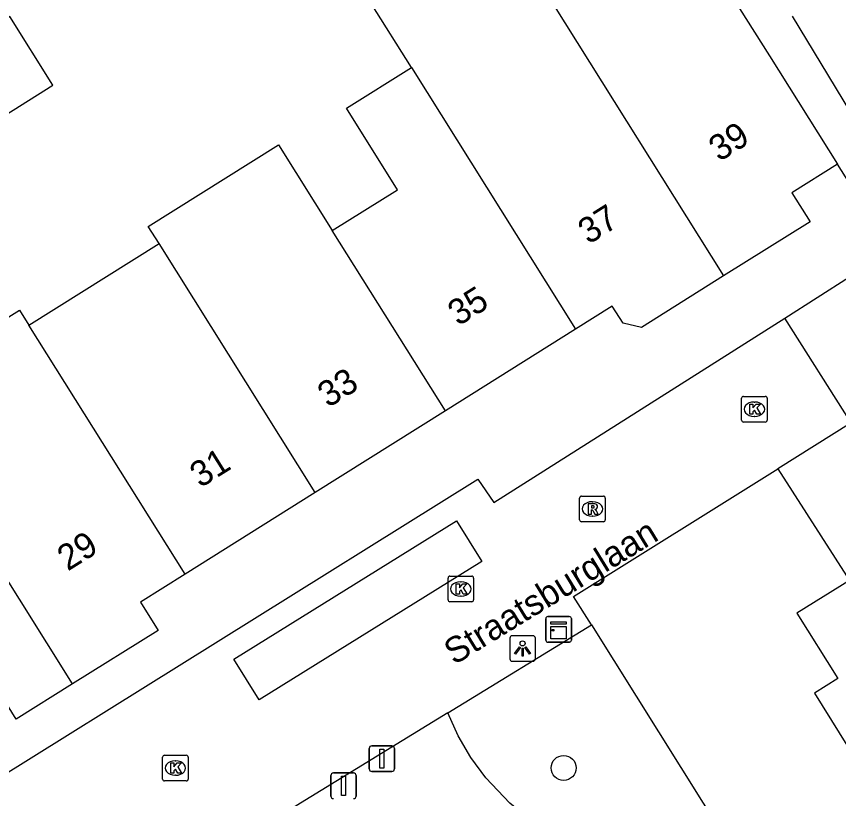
# Model space of a CAD drawing. Extents: x 157767 to 159171, y 387842 to 389425.
# Drawn here: x 158662.43 to 158694.55, y 388250.18 to 388280.75 of the extents above; entities that cross this region are included whole.
import ezdxf

# ---------------------------------------------------------------- set-up
doc = ezdxf.new("R2010")
doc.units = 0
for name, color, linetype in [('IMGEO_Afsluitpaal', 7, 'Continuous'), ('IMGEO_Boom', 7, 'Continuous'), ('IMGEO_Groenvoorziening', 7, 'Continuous'), ('IMGEO_Kast', 7, 'Continuous'), ('IMGEO_Kolk', 7, 'Continuous'), ('IMGEO_Lichtpunt', 7, 'Continuous'), ('IMGEO_Muur', 7, 'Continuous'), ('IMGEO_Openbare_ruimte_label', 7, 'Continuous'), ('IMGEO_Pand', 7, 'Continuous'), ('IMGEO_Pand_nummerreeks', 7, 'Continuous'), ('IMGEO_Rijbaan_lokaal_open', 7, 'Continuous'), ('IMGEO_Rioolput', 7, 'Continuous'), ('IMGEO_Voetpad_open', 7, 'Continuous')]:
    doc.layers.add(name, color=color, linetype=linetype)

msp = doc.modelspace()

# ---------------------------------------------------------------- linework, layer by layer
at = {"layer": 'IMGEO_Afsluitpaal'}
for p, q in [((158676.307, 388252.237), (158677.097, 388252.237)), ((158677.097, 388252.237), (158676.307, 388252.237)), ((158676.207, 388251.337), (158676.207, 388252.137)), ((158676.207, 388252.137), (158676.207, 388251.337)), ((158677.197, 388252.137), (158677.197, 388251.337)), ((158677.197, 388251.337), (158677.197, 388252.137)), ((158677.097, 388251.237), (158676.307, 388251.237)), ((158676.307, 388251.237), (158677.097, 388251.237)), ((158674.71, 388250.278), (158674.71, 388251.078)), ((158674.71, 388251.078), (158674.71, 388250.278)), ((158674.81, 388251.178), (158675.6, 388251.178)), ((158675.6, 388251.178), (158674.81, 388251.178)), ((158675.7, 388251.078), (158675.7, 388250.278)), ((158675.7, 388250.278), (158675.7, 388251.078))]:
    msp.add_line(p, q, dxfattribs=at)
for points in [[(158676.627, 388252.112), (158676.777, 388252.112), (158676.777, 388251.362), (158676.627, 388251.362), (158676.627, 388252.112)], [(158675.13, 388251.053), (158675.28, 388251.053), (158675.28, 388250.303), (158675.13, 388250.303), (158675.13, 388251.053)]]:
    msp.add_lwpolyline(points, dxfattribs=at)
for centre, start, end in [((158676.307, 388252.137), 90, 180), ((158676.307, 388252.137), 90, 180), ((158677.097, 388252.137), 0, 90), ((158677.097, 388252.137), 360, 90), ((158676.307, 388251.337), 180, 270), ((158676.307, 388251.337), 180, 270), ((158677.097, 388251.337), 270, 0), ((158677.097, 388251.337), 270, 0), ((158674.81, 388251.078), 90, 180), ((158674.81, 388251.078), 90, 180), ((158675.6, 388251.078), 0, 90), ((158675.6, 388251.078), 360, 90), ((158674.81, 388250.278), 180, 270), ((158674.81, 388250.278), 180, 270), ((158675.6, 388250.278), 270, 0), ((158675.6, 388250.278), 270, 0)]:
    msp.add_arc(centre, 0.1, start, end, dxfattribs=at)
at = {"layer": 'IMGEO_Boom'}
msp.add_circle((158683.805, 388251.375), 0.489, dxfattribs=at)
at = {"layer": 'IMGEO_Groenvoorziening'}
msp.add_lwpolyline([(158696.668, 388238.183), (158694.905, 388237.153), (158694.43, 388236.939), (158693.909, 388236.937), (158693.432, 388237.147), (158693.064, 388237.565), (158689.892, 388242.059), (158688.18, 388244.196), (158686.325, 388246.211), (158681.698, 388249.994), (158680.762, 388250.987), (158680.18, 388251.781), (158679.685, 388252.632), (158679.282, 388253.53)], dxfattribs=at)
at = {"layer": 'IMGEO_Kast'}
for p, q in [((158683.11, 388256.365), (158683.11, 388257.206)), ((158683.11, 388257.206), (158683.11, 388256.365)), ((158683.185, 388257.29), (158684.026, 388257.29)), ((158684.026, 388257.29), (158683.185, 388257.29)), ((158684.11, 388257.215), (158684.11, 388256.374)), ((158684.11, 388256.374), (158684.11, 388257.215)), ((158684.035, 388256.29), (158683.194, 388256.29)), ((158683.194, 388256.29), (158684.035, 388256.29))]:
    msp.add_line(p, q, dxfattribs=at)
for points in [[(158683.305, 388257.08), (158683.905, 388257.08), (158683.905, 388256.995), (158683.305, 388256.995), (158683.305, 388257.08)], [(158683.305, 388256.905), (158683.905, 388256.905), (158683.905, 388256.416), (158683.305, 388256.416), (158683.305, 388256.905)]]:
    msp.add_lwpolyline(points, dxfattribs=at)
msp.add_circle((158683.389, 388256.754), 0.0377, dxfattribs=at)
for centre, start, end in [((158683.188, 388257.212), 92.4484, 184.2845), ((158683.188, 388257.212), 92.4484, 184.2845), ((158684.032, 388257.212), 2.4484, 94.2845), ((158684.032, 388257.212), 2.4484, 94.2845), ((158683.188, 388256.368), 182.4484, 274.2845), ((158683.188, 388256.368), 182.4484, 274.2845), ((158684.032, 388256.368), 272.4484, 4.2845), ((158684.032, 388256.368), 272.4484, 4.2845)]:
    msp.add_arc(centre, 0.0779, start, end, dxfattribs=at)
at = {"layer": 'IMGEO_Kolk'}
for p, q in [((158690.758, 388264.969), (158690.758, 388265.821)), ((158690.833, 388265.895), (158691.685, 388265.895)), ((158691.246, 388265.675), (158691.271, 388265.675)), ((158691.759, 388265.821), (158691.759, 388264.969)), ((158691.269, 388265.115), (158691.244, 388265.115)), ((158691.685, 388264.895), (158690.833, 388264.895)), ((158679.288, 388257.945), (158679.288, 388258.797)), ((158679.363, 388258.871), (158680.215, 388258.871)), ((158679.776, 388258.651), (158679.801, 388258.651)), ((158680.289, 388258.797), (158680.289, 388257.945)), ((158679.799, 388258.091), (158679.774, 388258.091)), ((158680.215, 388257.871), (158679.363, 388257.871)), ((158668.21, 388251.869), (158669.062, 388251.869)), ((158668.135, 388250.943), (158668.135, 388251.795)), ((158668.623, 388251.649), (158668.648, 388251.649)), ((158669.136, 388251.795), (158669.136, 388250.943)), ((158669.062, 388250.869), (158668.21, 388250.869)), ((158668.646, 388251.089), (158668.621, 388251.089))]:
    msp.add_line(p, q, dxfattribs=at)
for points in [[(158690.758, 388264.969), (158690.758, 388265.821)], [(158690.833, 388265.895), (158691.685, 388265.895)], [(158691.759, 388265.821), (158691.759, 388264.969)], [(158691.079, 388265.595), (158691.202, 388265.595), (158691.202, 388265.444), (158691.332, 388265.595), (158691.496, 388265.595), (158691.35, 388265.444), (158691.503, 388265.195), (158691.351, 388265.195), (158691.266, 388265.359), (158691.202, 388265.292), (158691.202, 388265.195), (158691.079, 388265.195), (158691.079, 388265.595)], [(158691.685, 388264.895), (158690.833, 388264.895)], [(158679.288, 388257.945), (158679.288, 388258.797)], [(158679.363, 388258.871), (158680.215, 388258.871)], [(158680.289, 388258.797), (158680.289, 388257.945)], [(158679.609, 388258.571), (158679.732, 388258.571), (158679.732, 388258.42), (158679.862, 388258.571), (158680.026, 388258.571), (158679.88, 388258.42), (158680.033, 388258.171), (158679.881, 388258.171), (158679.796, 388258.335), (158679.732, 388258.268), (158679.732, 388258.171), (158679.609, 388258.171), (158679.609, 388258.571)], [(158680.215, 388257.871), (158679.363, 388257.871)], [(158668.21, 388251.869), (158669.062, 388251.869)], [(158668.135, 388250.943), (158668.135, 388251.795)], [(158668.456, 388251.569), (158668.579, 388251.569), (158668.579, 388251.418), (158668.709, 388251.569), (158668.873, 388251.569), (158668.727, 388251.418), (158668.88, 388251.169), (158668.728, 388251.169), (158668.643, 388251.333), (158668.579, 388251.266), (158668.579, 388251.169), (158668.456, 388251.169), (158668.456, 388251.569)], [(158669.136, 388251.795), (158669.136, 388250.943)], [(158669.062, 388250.869), (158668.21, 388250.869)]]:
    msp.add_lwpolyline(points, dxfattribs=at)
for centre, start, end in [((158690.835, 388265.819), 91.552, 178.448), ((158690.835, 388265.819), 91.552, 178.448), ((158691.683, 388265.819), 1.552, 88.448), ((158691.683, 388265.819), 1.552, 88.448), ((158690.835, 388264.971), 181.552, 268.448), ((158690.835, 388264.971), 181.552, 268.448), ((158691.683, 388264.971), 271.552, 358.448), ((158691.683, 388264.971), 271.552, 358.448), ((158679.365, 388258.795), 91.552, 178.448), ((158679.365, 388258.795), 91.552, 178.448), ((158680.213, 388258.795), 1.552, 88.448), ((158680.213, 388258.795), 1.552, 88.448), ((158679.365, 388257.947), 181.552, 268.448), ((158679.365, 388257.947), 181.552, 268.448), ((158680.213, 388257.947), 271.552, 358.448), ((158680.213, 388257.947), 271.552, 358.448), ((158668.212, 388251.793), 91.552, 178.448), ((158668.212, 388251.793), 91.552, 178.448), ((158669.06, 388251.793), 1.552, 88.448), ((158669.06, 388251.793), 1.552, 88.448), ((158668.212, 388250.945), 181.552, 268.448), ((158668.212, 388250.945), 181.552, 268.448), ((158669.06, 388250.945), 271.552, 358.448), ((158669.06, 388250.945), 271.552, 358.448)]:
    msp.add_arc(centre, 0.0765, start, end, dxfattribs=at)
for centre, major_axis, ratio, start_param, end_param in [((158691.245, 388265.395), (-0.387, 0.002), 0.722429, 4.712389, 7.853982), ((158691.27, 388265.395), (-0.39, 0.002), 0.717154, 1.570796, 4.712389), ((158679.775, 388258.371), (-0.387, 0.002), 0.722429, 4.712389, 7.853982), ((158679.8, 388258.371), (-0.39, 0.002), 0.717154, 1.570796, 4.712389), ((158668.622, 388251.369), (-0.387, 0.002), 0.722429, 4.712389, 7.853982), ((158668.647, 388251.369), (-0.39, 0.002), 0.717154, 1.570796, 4.712389)]:
    msp.add_ellipse(centre, major_axis=major_axis, ratio=ratio, start_param=start_param, end_param=end_param, dxfattribs=at)
at = {"layer": 'IMGEO_Lichtpunt'}
for p, q in [((158681.704, 388256.446), (158681.704, 388255.639)), ((158681.704, 388256.446), (158681.704, 388255.639)), ((158682.606, 388256.541), (158681.798, 388256.541)), ((158682.606, 388256.541), (158681.798, 388256.541)), ((158682.7, 388255.639), (158682.7, 388256.446)), ((158682.7, 388255.639), (158682.7, 388256.446)), ((158681.798, 388255.545), (158682.606, 388255.545)), ((158681.798, 388255.545), (158682.606, 388255.545))]:
    msp.add_line(p, q, dxfattribs=at)
for points in [[(158682.078, 388256.11), (158682.117, 388256.082), (158681.929, 388255.82), (158681.891, 388255.847), (158682.078, 388256.11)], [(158682.18, 388256.062), (158682.227, 388256.062), (158682.227, 388255.74), (158682.18, 388255.74), (158682.18, 388256.062)], [(158682.29, 388256.082), (158682.328, 388256.109), (158682.515, 388255.847), (158682.476, 388255.819), (158682.29, 388256.082)]]:
    msp.add_lwpolyline(points, dxfattribs=at)
msp.add_circle((158682.203, 388256.244), 0.0994, dxfattribs=at)
for centre, start, end in [((158681.798, 388256.446), 90, 180), ((158681.798, 388256.446), 90, 180), ((158682.606, 388256.446), 0, 90), ((158682.606, 388256.446), 0, 90), ((158681.798, 388255.639), 180, 270), ((158681.798, 388255.639), 180, 270), ((158682.606, 388255.639), 270, 0), ((158682.606, 388255.639), 270, 360)]:
    msp.add_arc(centre, 0.0946, start, end, dxfattribs=at)
at = {"layer": 'IMGEO_Muur'}
msp.add_lwpolyline([(158695.044, 388264.857), (158692.172, 388263.06)], dxfattribs=at)
at = {"layer": 'IMGEO_Pand'}
for points in [[(158677.859, 388278.751), (158676.288, 388281.256), (158681.369, 388284.444), (158682.944, 388281.941), (158683.37, 388281.264)], [(158688.453, 388284.454), (158688.522, 388284.497), (158690.093, 388281.993), (158691.844, 388279.201), (158694.501, 388274.966)], [(158683.37, 388281.264), (158690.055, 388270.603)], [(158662.166, 388280.741), (158659.65, 388279.165), (158661.334, 388276.478), (158663.85, 388278.055), (158662.166, 388280.741)], [(158697.019, 388273.699), (158694.43, 388277.977), (158692.751, 388280.75)], [(158674.767, 388272.378), (158677.311, 388273.975), (158675.316, 388277.156), (158677.859, 388278.751)], [(158677.859, 388278.751), (158684.274, 388268.522)], [(158667.998, 388271.867), (158667.578, 388272.536), (158672.666, 388275.727), (158674.767, 388272.378)], [(158694.501, 388274.966), (158692.723, 388273.851), (158693.432, 388272.722), (158690.055, 388270.603)], [(158679.187, 388265.331), (158674.767, 388272.378)], [(158662.912, 388268.676), (158667.998, 388271.867)], [(158674.099, 388262.139), (158667.998, 388271.867)], [(158690.055, 388270.603), (158686.842, 388268.588), (158686.126, 388268.752), (158685.707, 388269.421), (158684.274, 388268.522)], [(158657.453, 388266.081), (158662.539, 388269.271), (158662.912, 388268.676)], [(158669.013, 388258.948), (158662.912, 388268.676)], [(158684.274, 388268.522), (158679.187, 388265.331)], [(158664.616, 388254.657), (158657.453, 388266.081)], [(158679.187, 388265.331), (158674.099, 388262.139)], [(158674.099, 388262.139), (158669.013, 388258.948)], [(158669.013, 388258.948), (158667.267, 388257.853), (158667.957, 388256.753), (158664.616, 388254.657)], [(158694.97, 388258.704), (158692.92, 388257.419), (158694.515, 388254.875), (158693.609, 388254.297), (158695.24, 388251.685)], [(158664.616, 388254.657), (158662.421, 388253.28), (158660.849, 388255.785), (158657.958, 388253.972)]]:
    msp.add_lwpolyline(points, dxfattribs=at)
at = {"layer": 'IMGEO_Rijbaan_lokaal_open'}
for points in [[(158692.444, 388268.959), (158694.978, 388270.565)], [(158638.374, 388244.398), (158639.543, 388245.129), (158643.296, 388239.491), (158660.15, 388250), (158680.456, 388262.662), (158681.074, 388261.752), (158692.444, 388268.959)], [(158695.044, 388264.857), (158692.444, 388268.959)], [(158695.044, 388264.857), (158692.172, 388263.06)], [(158684.888, 388256.968), (158684.197, 388258.07), (158692.172, 388263.06)], [(158692.172, 388263.06), (158694.97, 388258.704)], [(158671.906, 388254.04), (158670.919, 388255.631), (158679.619, 388261.031), (158680.607, 388259.439), (158671.906, 388254.04)], [(158679.282, 388253.53), (158684.888, 388256.968)], [(158684.888, 388256.968), (158689.258, 388250), (158696.668, 388238.183)], [(158679.282, 388253.53), (158673.529, 388250), (158673.038, 388249.699)]]:
    msp.add_lwpolyline(points, dxfattribs=at)
at = {"layer": 'IMGEO_Rioolput'}
for p, q in [((158684.43, 388261.073), (158684.43, 388261.925)), ((158684.505, 388261.999), (158685.357, 388261.999)), ((158685.431, 388261.925), (158685.431, 388261.073)), ((158684.918, 388261.779), (158684.943, 388261.779)), ((158684.941, 388261.219), (158684.916, 388261.219)), ((158685.357, 388260.999), (158684.505, 388260.999))]:
    msp.add_line(p, q, dxfattribs=at)
for points in [[(158684.43, 388261.073), (158684.43, 388261.925)], [(158684.505, 388261.999), (158685.357, 388261.999)], [(158685.431, 388261.925), (158685.431, 388261.073)], [(158685.019, 388261.697), (158684.767, 388261.699), (158684.767, 388261.299)], [(158684.945, 388261.618), (158684.891, 388261.618), (158684.891, 388261.537)], [(158684.891, 388261.537), (158684.943, 388261.537)], [(158684.767, 388261.299), (158684.891, 388261.299), (158684.891, 388261.461), (158684.902, 388261.461)], [(158684.949, 388261.432), (158685.02, 388261.299), (158685.16, 388261.299), (158685.095, 388261.425)], [(158685.357, 388260.999), (158684.505, 388260.999)]]:
    msp.add_lwpolyline(points, dxfattribs=at)
for centre, radius, start, end in [((158684.507, 388261.923), 0.0765, 91.552, 178.448), ((158684.507, 388261.923), 0.0765, 91.552, 178.448), ((158685.355, 388261.923), 0.0765, 1.552, 88.448), ((158685.355, 388261.923), 0.0765, 1.552, 88.448), ((158684.927, 388261.726), 0.19, 274.7715, 282.9687), ((158684.951, 388261.522), 0.0964, 77.0061, 93.1865), ((158684.965, 388261.579), 0.0378, 276.6634, 79.6772), ((158685.018, 388261.587), 0.109, 350.3612, 89.416), ((158685.016, 388261.587), 0.112, 277.5842, 350.9817), ((158685, 388261.372), 0.108, 29.5134, 73.7905), ((158684.901, 388261.408), 0.0533, 26.0293, 88.6989), ((158684.507, 388261.075), 0.0765, 181.552, 268.448), ((158684.507, 388261.075), 0.0765, 181.552, 268.448), ((158685.355, 388261.075), 0.0765, 271.552, 358.448), ((158685.355, 388261.075), 0.0765, 271.552, 358.448)]:
    msp.add_arc(centre, radius, start, end, dxfattribs=at)
for centre, major_axis, ratio, start_param, end_param in [((158684.917, 388261.499), (-0.387, 0.002), 0.722429, 4.712389, 7.853982), ((158684.942, 388261.499), (-0.39, 0.002), 0.717154, 1.570796, 4.712389)]:
    msp.add_ellipse(centre, major_axis=major_axis, ratio=ratio, start_param=start_param, end_param=end_param, dxfattribs=at)
at = {"layer": 'IMGEO_Voetpad_open'}
msp.add_lwpolyline([(158696.628, 388271.611), (158694.501, 388274.966)], dxfattribs=at)

# ---------------------------------------------------------------- texts
at = {"layer": 'IMGEO_Openbare_ruimte_label'}
msp.add_text('Straatsburglaan', height=1, rotation=31.5137, dxfattribs=at).set_placement((158679.531, 388255.379))
at = {"layer": 'IMGEO_Pand_nummerreeks'}
for s, rotation, p in [('39', 32.0914, (158689.885, 388275.047)), ('37', 32.1028, (158684.778, 388271.814)), ('35', 32.1021, (158679.691, 388268.622)), ('33', 32.1021, (158674.604, 388265.431)), ('31', 32.1021, (158669.613, 388262.299)), ('29', 32.0988, (158664.431, 388259.048))]:
    msp.add_text(s, height=1, rotation=rotation, dxfattribs=at).set_placement(p)

doc.saveas('drawing.dxf')
